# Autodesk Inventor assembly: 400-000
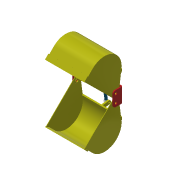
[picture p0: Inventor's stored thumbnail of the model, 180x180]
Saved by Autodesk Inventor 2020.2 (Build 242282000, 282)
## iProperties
Created: 2014-01
Part Number: 400-000
Document SubType Name: Assembly
Designer: F.Stasiak
Manager: www.cadconsulting.pl
Company: Fabian Stasiak CAD Consulting
Author: F.Stasiak
Subject: Zbiór ćwiczeń. Autodesk Inventor 2020. Kurs podstawowy
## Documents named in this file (4)
- C:\2020_Kurs_podstawowy\R6 Zespoły\Warsztat\Gotowe\400-000_Gotowy_W.iam
- C:\2020_Kurs_podstawowy\R6 Zespoły\Warsztat\Komponenty\400-001.ipt
- C:\2020_Kurs_podstawowy\R6 Zespoły\Warsztat\Komponenty\400-002.ipt
- C:\2020_Kurs_podstawowy\R6 Zespoły\Warsztat\Komponenty\S-100W.iam
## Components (5 placed, 3 different names)
1. 400-001:1 — Wstaw:1, Wstaw:2, Wstaw:5
2. 400-002:1 — Wstaw:2, Wstaw:6
3. 400-002:2 — Wstaw:1, Wstaw:4
4. S-100W:1 [sub-assembly] — Wstaw:4
5. S-100W:2 [sub-assembly] — Wstaw:5, Wstaw:6
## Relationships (5: Insert 5)
- Wstaw:1 [Insert]: 400-001:1 ↔ 400-002:2
- Wstaw:2 [Insert]: 400-001:1 ↔ 400-002:1
- Wstaw:4 [Insert]: 400-002:2 ↔ S-100W:1
- Wstaw:5 [Insert]: 400-001:1 ↔ S-100W:2
- Wstaw:6 [Insert]: 400-002:1 ↔ S-100W:2
